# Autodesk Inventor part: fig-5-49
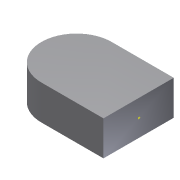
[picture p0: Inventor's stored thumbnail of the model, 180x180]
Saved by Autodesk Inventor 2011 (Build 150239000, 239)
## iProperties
Created: 2010-02
Part Number: fig-5-49
Document SubType Name: Modeling
Designer: CADSoft
Density: 1 g/cm^3
Author: CADSoft
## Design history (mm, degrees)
sketch "Sketch1"
  geometry: L1 (-17.92, 20.292)-(0, 20.292); L2 (0, 20.292)-(0, 0); L3 (0, 0)-(-17.92, 0); A1 r 10.146 centre (-17.92, 10.146) between (-17.92, 20.292) and (-17.92, 0)
  constraints: 6 end point, 2 horizontal, 2 point on circle, 2 tangent, 1 centre point, 1 vertical
extrude "Extrusion1" new body sketch "Sketch1" distance "d0" = 10; taper "d1" = 0 deg
workpoint "Work Point1"
body "Solid1"
